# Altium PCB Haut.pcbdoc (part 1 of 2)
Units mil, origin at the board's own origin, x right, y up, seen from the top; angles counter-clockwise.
Board outline 4330.8 x 4330.8 mil, 2 copper layers (Top Layer, Bottom Layer), stack 62.2 mil thick; 77 components, 45 nets, 290 pads, 215 vias.
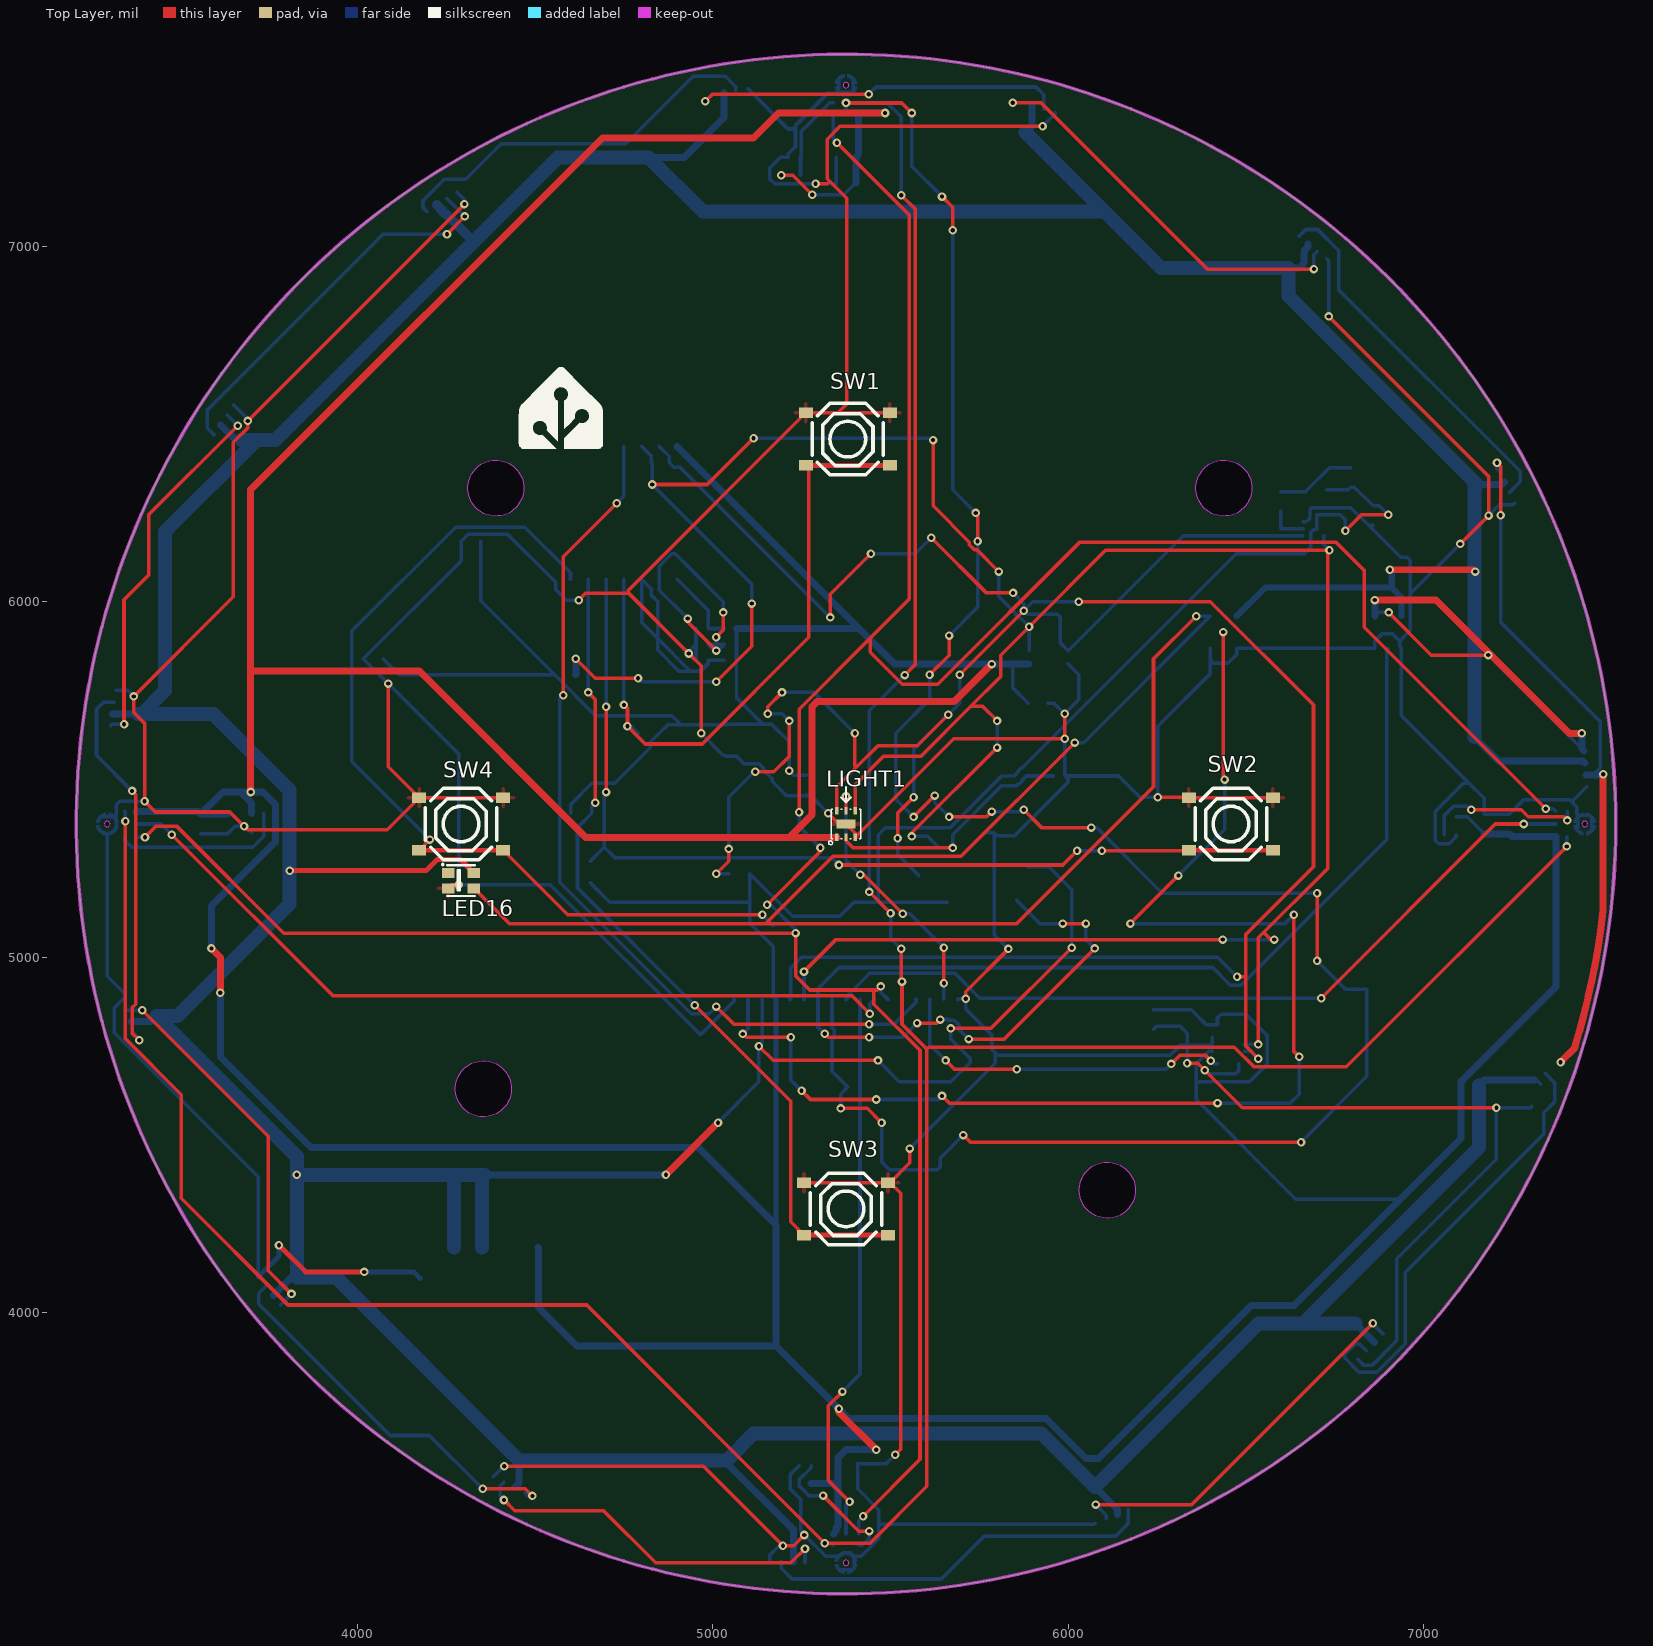
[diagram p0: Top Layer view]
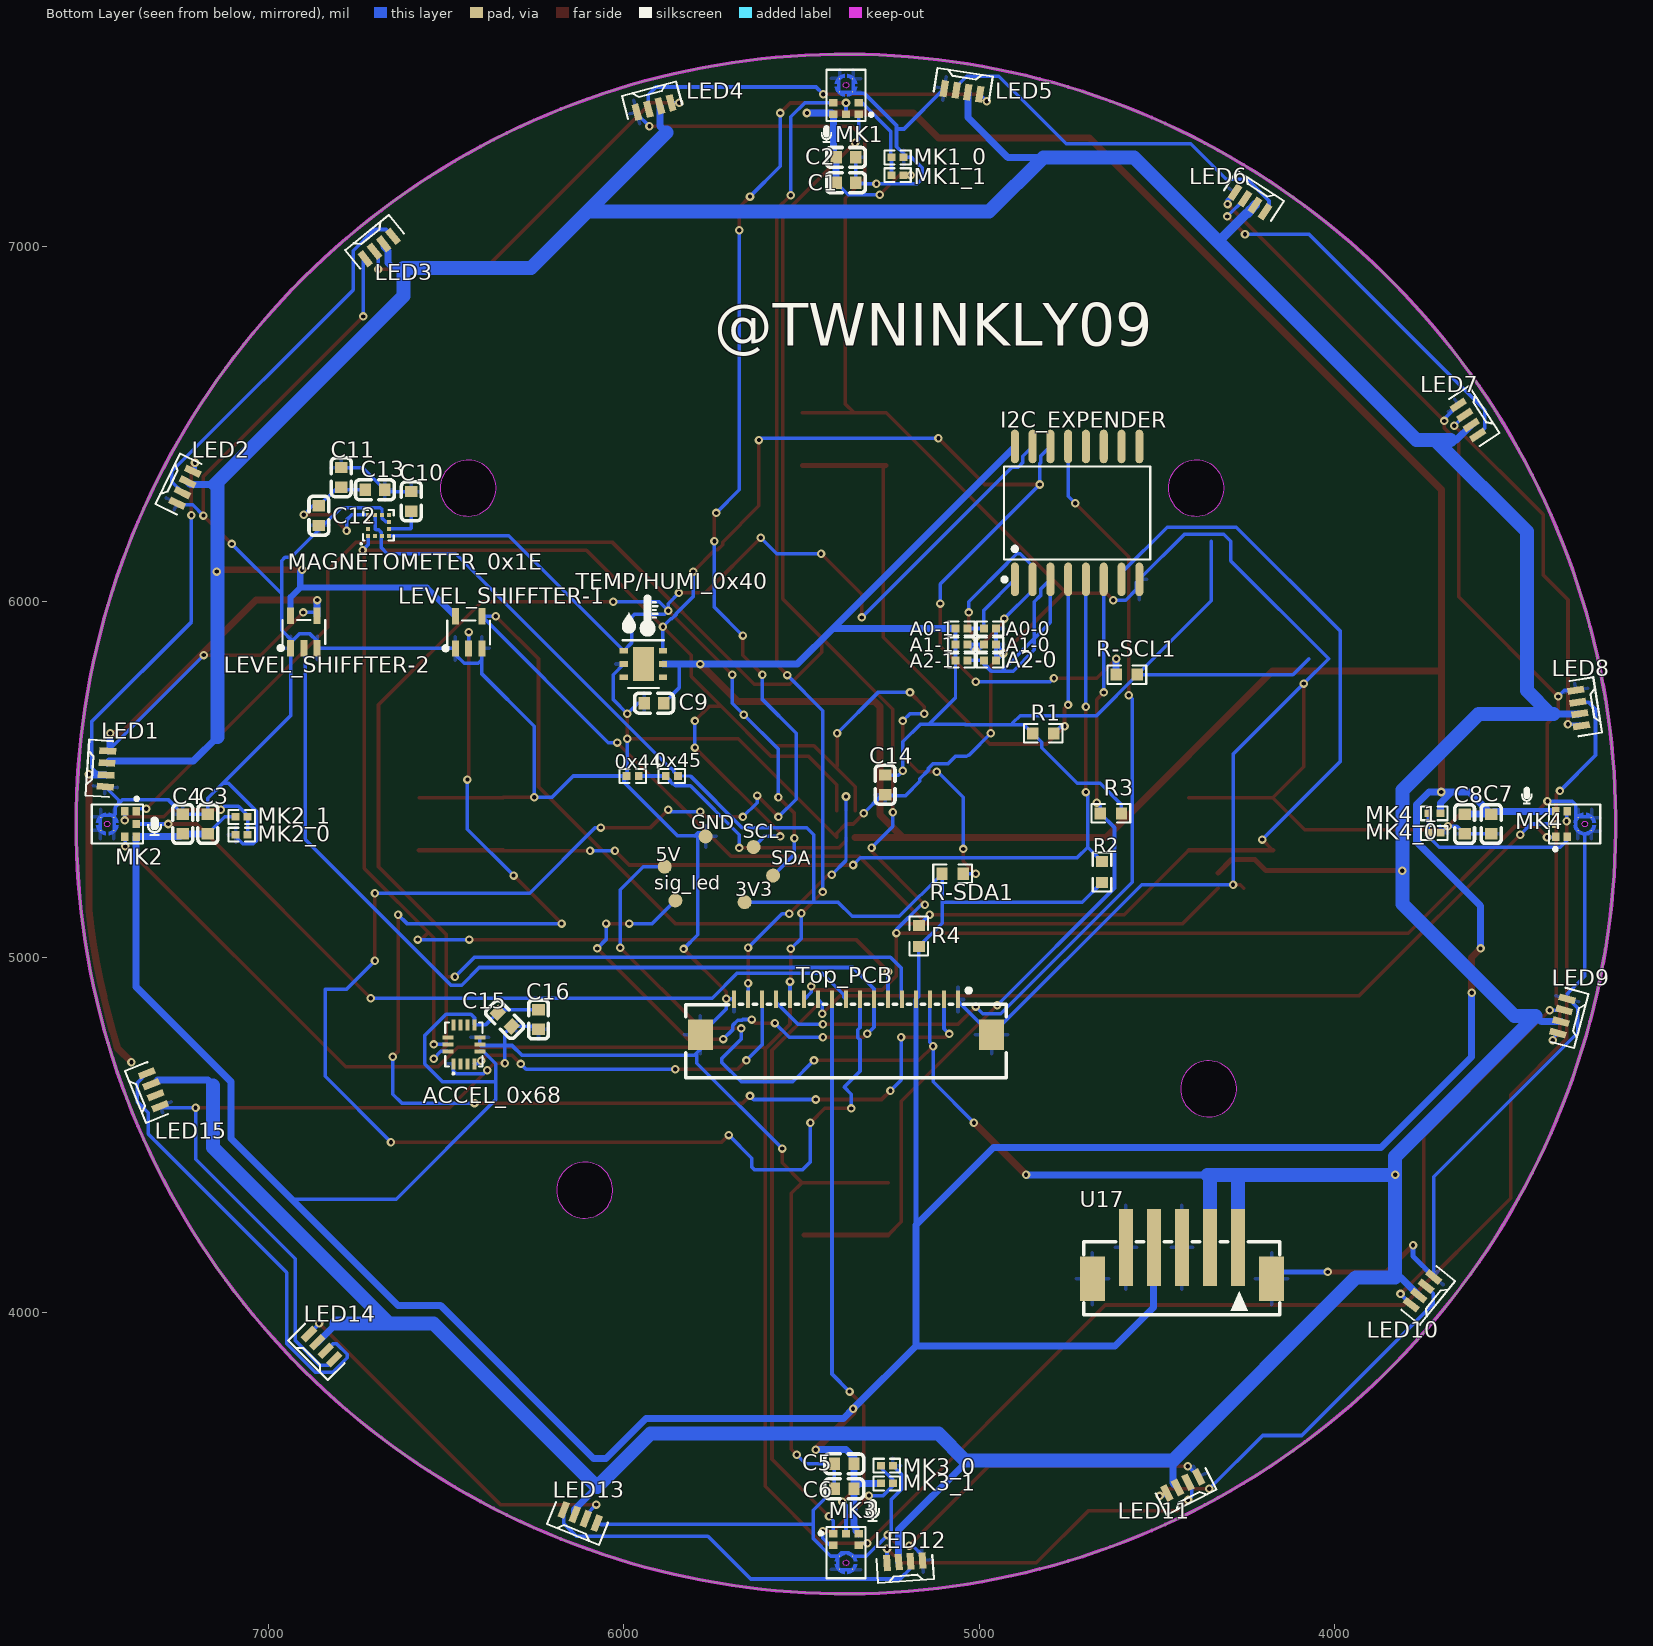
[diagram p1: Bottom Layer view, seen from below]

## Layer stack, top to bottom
Top Solder Mask Layer: solder mask 0.4, Dk 3.3
Top Layer: signal copper 1.4
Dielectric1: surface 59.4, FR4, Dk 4.5
Bottom Layer: signal copper 1.4
Bottom Solder Mask Layer: solder mask 0.4, Dk 3.3

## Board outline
7539.8,5374.4 ccw(c5374.4,5374.4) 3209.1,5374.4 ccw(c5374.4,5374.4)
cut-out: 4433.1,4629.4 4432.8,4621.6 4431.6,4613.8 4429.6,4606.2 4427,4598.8 4423.6,4591.7 4419.5,4585 4414.7,4578.8 4409.4,4573 4403.5,4567.8 4397.1,4563.3 4390.3,4559.3 4383.2,4556.1 4375.7,4553.6 4368.1,4551.9 4360.3,4550.9 4352.4,4550.7 4344.6,4551.3 4336.9,4552.6 4329.3,4554.8 4322,4557.6 4315,4561.2 4308.4,4565.5 4302.3,4570.4 4296.7,4575.8 4291.6,4581.9 4287.2,4588.3 4283.5,4595.2 4280.4,4602.5 4278.1,4610 4276.5,4617.7 4275.8,4625.5 4275.8,4633.3 4276.5,4641.1 4278.1,4648.8 4280.4,4656.3 4283.5,4663.6 4287.2,4670.5 4291.6,4676.9 4296.7,4683 4302.3,4688.4 4308.4,4693.3 4315,4697.6 4322,4701.2 4329.3,4704 4336.9,4706.2 4344.6,4707.5 4352.4,4708.1 4360.3,4707.9 4368.1,4706.9 4375.7,4705.2 4383.2,4702.7 4390.3,4699.5 4397.1,4695.5 4403.5,4691 4409.4,4685.8 4414.7,4680 4419.5,4673.8 4423.6,4667.1 4427,4660 4429.6,4652.6 4431.6,4645 4432.8,4637.2
cut-out: 4468.1,6319.3 4467.8,6311.4 4466.6,6303.7 4464.6,6296.1 4462,6288.7 4458.6,6281.6 4454.5,6274.9 4449.7,6268.7 4444.4,6262.9 4438.5,6257.7 4432.1,6253.1 4425.3,6249.2 4418.2,6246 4410.7,6243.5 4403.1,6241.7 4395.3,6240.8 4387.4,6240.6 4379.6,6241.2 4371.9,6242.5 4364.3,6244.6 4357,6247.5 4350,6251.1 4343.4,6255.4 4337.3,6260.2 4331.7,6265.7 4326.6,6271.7 4322.2,6278.2 4318.5,6285.1 4315.4,6292.4 4313.1,6299.9 4311.5,6307.5 4310.8,6315.4 4310.8,6323.2 4311.5,6331 4313.1,6338.7 4315.4,6346.2 4318.5,6353.4 4322.2,6360.3 4326.6,6366.8 4331.7,6372.8 4337.3,6378.3 4343.4,6383.2 4350,6387.5 4357,6391.1 4364.3,6393.9 4371.9,6396.1 4379.6,6397.4 4387.4,6398 4395.3,6397.8 4403.1,6396.8 4410.7,6395.1 4418.2,6392.6 4425.3,6389.4 4432.1,6385.4 4438.5,6380.8 4444.4,6375.7 4449.7,6369.9 4454.5,6363.6 4458.6,6356.9 4462,6349.9 4464.6,6342.5 4466.6,6334.9 4467.8,6327.1
cut-out: 6516.1,6319.3 6515.7,6311.4 6514.6,6303.7 6512.6,6296.1 6510,6288.7 6506.6,6281.6 6502.5,6274.9 6497.7,6268.7 6492.4,6262.9 6486.5,6257.7 6480.1,6253.1 6473.3,6249.2 6466.2,6246 6458.7,6243.5 6451.1,6241.7 6443.3,6240.8 6435.4,6240.6 6427.6,6241.2 6419.9,6242.5 6412.3,6244.6 6405,6247.5 6398,6251.1 6391.4,6255.4 6385.3,6260.2 6379.7,6265.7 6374.6,6271.7 6370.2,6278.2 6366.5,6285.1 6363.4,6292.4 6361.1,6299.9 6359.5,6307.5 6358.8,6315.4 6358.8,6323.2 6359.5,6331 6361.1,6338.7 6363.4,6346.2 6366.5,6353.4 6370.2,6360.3 6374.6,6366.8 6379.7,6372.8 6385.3,6378.3 6391.4,6383.2 6398,6387.5 6405,6391.1 6412.3,6393.9 6419.9,6396.1 6427.6,6397.4 6435.4,6398 6443.3,6397.8 6451.1,6396.8 6458.7,6395.1 6466.2,6392.6 6473.3,6389.4 6480.1,6385.4 6486.5,6380.8 6492.4,6375.7 6497.7,6369.9 6502.5,6363.6 6506.6,6356.9 6510,6349.9 6512.6,6342.5 6514.6,6334.9 6515.7,6327.1
cut-out: 6188.1,4344.4 6187.8,4336.6 6186.6,4328.8 6184.6,4321.2 6182,4313.8 6178.6,4306.7 6174.5,4300 6169.7,4293.8 6164.4,4288 6158.5,4282.8 6152.1,4278.3 6145.3,4274.3 6138.2,4271.1 6130.7,4268.6 6123.1,4266.9 6115.3,4265.9 6107.4,4265.7 6099.6,4266.3 6091.9,4267.6 6084.3,4269.8 6077,4272.6 6070,4276.2 6063.4,4280.5 6057.3,4285.4 6051.7,4290.8 6046.6,4296.9 6042.2,4303.3 6038.5,4310.2 6035.4,4317.5 6033.1,4325 6031.5,4332.7 6030.8,4340.5 6030.8,4348.3 6031.5,4356.1 6033.1,4363.8 6035.4,4371.3 6038.5,4378.6 6042.2,4385.5 6046.6,4391.9 6051.7,4398 6057.3,4403.4 6063.4,4408.3 6070,4412.6 6077,4416.2 6084.3,4419 6091.9,4421.2 6099.6,4422.5 6107.4,4423.1 6115.3,4422.9 6123.1,4421.9 6130.7,4420.2 6138.2,4417.7 6145.3,4414.5 6152.1,4410.5 6158.5,4406 6164.4,4400.8 6169.7,4395 6174.5,4388.8 6178.6,4382.1 6182,4375 6184.6,4367.6 6186.6,4360 6187.8,4352.2

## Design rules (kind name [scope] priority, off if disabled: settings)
BoardOutlineClearance copperThickness1oz [All] p0: genericclearance=10 ignorepadtopadclearanceinfootprint=FALSE except(0: Arc-SplitContinuation Track-SplitContinuation SMDPad-SplitContinuation THPad-SplitContinuation Via-SplitContinuation Fill-SplitContinuation Poly-SplitContinuation Region-SplitContinuation Text-SplitContinuation)
BoardOutlineClearance copperThickness2oz [All] p0: genericclearance=10 ignorepadtopadclearanceinfootprint=FALSE except(0: Arc-SplitContinuation Track-SplitContinuation SMDPad-SplitContinuation THPad-SplitContinuation Via-SplitContinuation Fill-SplitContinuation Poly-SplitContinuation Region-SplitContinuation Text-SplitContinuation)
BoardOutlineClearance Plane_innerPlane [All] p0: genericclearance=10 ignorepadtopadclearanceinfootprint=FALSE except(0: Arc-SplitContinuation Track-SplitContinuation SMDPad-SplitContinuation THPad-SplitContinuation Via-SplitContinuation Fill-SplitContinuation Poly-SplitContinuation Region-SplitContinuation Text-SplitContinuation)
BoardOutlineClearance Copper_copperRegion [All] p0: genericclearance=10 ignorepadtopadclearanceinfootprint=FALSE except(0: Arc-SplitContinuation Track-SplitContinuation SMDPad-SplitContinuation THPad-SplitContinuation Via-SplitContinuation Fill-SplitContinuation Poly-SplitContinuation Region-SplitContinuation Text-SplitContinuation)
BoardOutlineClearance otherClearance [All] p0: genericclearance=10 ignorepadtopadclearanceinfootprint=FALSE except(0: Arc-SplitContinuation Track-SplitContinuation SMDPad-SplitContinuation THPad-SplitContinuation Via-SplitContinuation Fill-SplitContinuation Poly-SplitContinuation Region-SplitContinuation Text-SplitContinuation)
Clearance copperThickness1oz [All] p1: gap=7 ignorepadtopadclearanceinfootprint=FALSE
Clearance copperThickness2oz [All] p1: gap=7 ignorepadtopadclearanceinfootprint=FALSE
Clearance Plane_innerPlane [All] p1: gap=7 ignorepadtopadclearanceinfootprint=FALSE
Clearance Copper_copperRegion [All] p1: gap=7 ignorepadtopadclearanceinfootprint=FALSE
Clearance otherClearance [All] p1: gap=7 ignorepadtopadclearanceinfootprint=FALSE
DiffPairsRouting differentialPair [All] p1: maxuncoupledlength=10 minlimit=6 maxlimit=Infinity mostfreqgap=6 toplayer_minwidth=5 toplayer_prefwidth=10 toplayer_maxwidth=100 bottomlayer_minwidth=5 bottomlayer_prefwidth=10 bottomlayer_maxwidth=100
PasteMaskExpansion pasteMaskExpansion [All] p1: expansion=0
PlaneConnect innerPlane [All] p1: planeconnectstyle=Relief reliefexpansion=20 reliefentries=4 reliefconductorwidth=10 reliefairgap=10
PolygonConnect copperRegion [All] p1: connectstyle=Relief reliefentries=4 reliefconductorwidth=10 polygonreliefangle="90 Angle" airgapwidth=10
RoutingVias viaSize [All] p1: viastyle="Through Hole" holewidth=12.0078 minholewidth=11.811 maxholewidth=248.0314 width=12.0078 minwidth=11.811 maxwidth=248.0314
SolderMaskExpansion solderMaskExpansion [IsVia] p1: useseparateexpansions=TRUE expansion=-1000 expansionbottom=-1000
SolderMaskExpansion solderMaskExpansion [All] p2: useseparateexpansions=TRUE expansion=2 expansionbottom=2
Width copperThickness1oz [All] p1: maxlimit=100 minlimit=5 preferedwidth=10
Width copperThickness2oz [All] p1: maxlimit=100 minlimit=8 preferedwidth=10

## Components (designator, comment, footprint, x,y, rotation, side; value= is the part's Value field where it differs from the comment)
0x44 "0Ω" R0402 5974.4,5509.4 r180 bottom
0x45 "0Ω" R0402 5864.4,5509.4 r180 bottom
3V3 "" Test-Point-0.5mm 5659.4,5154.4 r180 bottom
5V "" Test-Point-0.5mm 5884.4,5254.4 r180 bottom
A0-0 "0Ω" R0402 4969.4,5924.4 r0 bottom locked
A0-1 "0Ω" R0402 5049.4,5924.4 r180 bottom locked
A1-0 "0Ω" R0402 4969.4,5879.4 r180 bottom locked
A1-1 "0Ω" R0402 5049.4,5879.4 r180 bottom locked
A2-0 "0Ω" R0402 4969.4,5834.4 r180 bottom locked
A2-1 "0Ω" R0402 5049.4,5834.4 r180 bottom locked
ACCEL_0x68 "BMI160" LGA-14_L3.0-W2.5-P0.50-BL 6449.4,4754.4 r180 bottom
C1 "200pF" C0603#1 5374.4,7178.1 r180 bottom
C2 "100nF" C0603#1 5374.4,7249.4 r180 bottom
C3 "200pF" C0603#1 7169.4,5374.4 r90 bottom
C4 "100nF" C0603#1 7240,5374.4 r90 bottom locked
C5 "200pF" C0603#1 5379.4,3574.4 r0 bottom
C6 "100nF" C0603#1 5379.4,3504.4 r0 bottom
C7 "200pF" C0603#1 3559.4,5374.4 r270 bottom
C8 "100nF" C0603#1 3634.4,5374.4 r270 bottom
C9 "100nF" C0603#1 5914.4,5714.4 r0 bottom
C10 "220nF" C0603#2 6597,6282 r270 bottom
C11 "100nF" C0603#1 6794.4,6349.4 r270 bottom
C12 "100nF" C0603#2 6857,6241.8 r90 bottom
C13 "10uF" C0603#1 6699.4,6314.4 r0 bottom
C14 "100nF" C0603#1 5264.4,5484.4 r90 bottom
C15 "100nF" C0603#1 6334.4,4824.4 r45 bottom
C16 "100nF" C0603#1 6239.4,4824.4 r90 bottom
GND "" Test-Point-0.5mm 5769.4,5339.4 r180 bottom
I2C_EXPENDER "PCA9554DW" SOIC-16_L10.3-W7.5-P1.27-LS10.3-BL 4724.4,6249.4 r180 bottom locked
LED1 "WS2812C-4020" LED-SMD_4P-L4.0-W1.7-R#1 7454.4,5529.4 r94 bottom locked
LED2 "WS2812C-4020" LED-SMD_4P-L4.0-W1.7-R#2 7233.6,6321.7 r116 bottom locked
LED3 "WS2812C-4020" LED-SMD_4P-L4.0-W1.7-R#3 6687.6,6996 r141 bottom locked
LED4 "WS2812C-4020" LED-SMD_4P-L4.0-W1.7-R#4 5914.5,7389.9 r165 bottom locked
LED5 "WS2812C-4020" LED-SMD_4P-L4.0-W1.7-R#5 5048,7435.3 r189 bottom locked
LED6 "WS2812C-4020" LED-SMD_4P-L4.0-W1.7-R#6 4238,7124.4 r213 bottom locked
LED7 "WS2812C-4020" LED-SMD_4P-L4.0-W1.7-R#1 3624.4,6510.9 r237 bottom locked
LED8 "WS2812C-4020" LED-SMD_4P-L4.0-W1.7-R#7 3313.5,5700.8 r261 bottom locked
LED9 "WS2812C-4020" LED-SMD_4P-L4.0-W1.7-R#8 3358.9,4834.3 r285 bottom locked
LED10 "WS2812C-4020" LED-SMD_4P-L4.0-W1.7-R#9 3752.8,4061.3 r309 bottom locked
LED11 "WS2812C-4020" LED-SMD_4P-L4.0-W1.7-R#1 4427.1,3515.2 r333 bottom locked
LED12 "WS2812C-4020" LED-SMD_4P-L4.0-W1.7-R#6 5209.4,3299.4 r356 bottom locked
LED13 "WS2812C-4020" LED-SMD_4P-L4.0-W1.7-R#10 6122.2,3426.4 r22 bottom locked
LED14 "WS2812C-4020" LED-SMD_4P-L4.0-W1.7-R#2 6849.4,3904.4 r45 bottom locked
LED15 "WS2812C-4020" LED-SMD_4P-L4.0-W1.7-R#11 7322.4,4626.6 r68 bottom locked
LED16 "WS2812B-2020" LED-SMD_4P-L2.0-W2.0-TL_WS2812B-2020 4291.7,5215.1 r0 top locked
LEVEL_SHIFFTER-1 "74AHCT1G125GV" SOT-23-5_L3.0-W1.7-P0.95-LS2.8-BL#1 6435.9,5913.6 r180 bottom
LEVEL_SHIFFTER-2 "74AHCT1G125GV" SOT-23-5_L3.0-W1.7-P0.95-LS2.8-BL#2 6899.4,5914.4 r180 bottom
LIGHT1 "OPT3001DNPR" USON6_L2.1-W2.1-P0.65-BL-EP 5374.4,5374.4 r0 top locked
MAGNETOMETER_0x1E "LIS2MDLTR" VLGA-12_L2.0-W2.0-P0.50-BL 6689.4,6214.4 r180 bottom
MK1 "SPH0645LM4H-B-8" MIC-SMD_6P-L3.5-W2.7-P0.90-BL#1 5374.4,7421.6 r90 bottom locked
MK1_0 "0Ω" R0402 5229.4,7249.4 r180 bottom
MK1_1 "0Ω" R0402 5229.4,7199.4 r180 bottom
MK2 "SPH0645LM4H-B-8" MIC-SMD_6P-L3.5-W2.7-P0.90-BL#2 7421.7,5374.4 r0 bottom locked
MK2_0 "0Ω" R0402 7074.4,5344.4 r0 bottom
MK2_1 "0Ω" R0402 7074.4,5394.4 r0 bottom
MK3 "SPH0645LM4H-B-8" MIC-SMD_6P-L3.5-W2.7-P0.90-BL#1 5374.4,3327.2 r270 bottom locked
MK3_0 "0Ω" R0402 5259.4,3569.4 r180 bottom
MK3_1 "0Ω" R0402 5259.4,3519.4 r0 bottom
MK4 "SPH0645LM4H-B-8" MIC-SMD_6P-L3.5-W2.7-P0.90-BL#1 3327.2,5374.4 r180 bottom locked
MK4_0 "0Ω" R0402 3719.4,5349.4 r180 bottom
MK4_1 "0Ω" R0402 3719.4,5404.4 r180 bottom
R1 "10kΩ" R0603 4819.4,5629.4 r180 bottom
R2 "10kΩ" R0603 4654.4,5239.4 r90 bottom
R3 "10kΩ" R0603 4629.4,5404.4 r0 bottom
R4 "10kΩ" R0603 5169.4,5059.4 r90 bottom
R-SCL1 "4.7kΩ" R0603 4584.4,5794.4 r180 bottom
R-SDA1 "4.7kΩ" R0603 5074.4,5234.4 r0 bottom
SCL "" Test-Point-0.5mm 5634.4,5309.4 r180 bottom
SDA "" Test-Point-0.5mm 5579.4,5229.4 r180 bottom
sig_led "sig_led" Test-Point-0.5mm 5854.4,5159.4 r180 bottom
SW1 "TS-1187A-B-A-B" SW-SMD_4P-L5.1-W5.1-P3.70-LS6.5-TL_H1.5 5379.4,6457.1 r0 top locked
SW2 "TS-1187A-B-A-B" SW-SMD_4P-L5.1-W5.1-P3.70-LS6.5-TL_H1.5 6457.1,5374.4 r0 top locked
SW3 "TS-1187A-B-A-B" SW-SMD_4P-L5.1-W5.1-P3.70-LS6.5-TL_H1.5 5374.4,4291.7 r0 top locked
SW4 "TS-1187A-B-A-B" SW-SMD_4P-L5.1-W5.1-P3.70-LS6.5-TL_H1.5 4291.7,5374.4 r0 top locked
TEMP/HUMI_0x40 "Sensor_Humidity_HDC1080" Package_SON:Texas_PWSON-N6 5944.4,5824.4 r180 bottom
Top_PCB "ZX-1.0FPC-2H-QFX17P" FPC-SMD_17P-P1.00_ZX-1.0FPC-2H-QFX17P 5374.4,4831.1 r180 bottom locked
U17 "B5B-PH-SM4-TB(LF)(SN)" CONN-SMD_5P-P2.00_B6B-PH-SM4-TB-LF-SN 4429.4,4139.4 r180 bottom

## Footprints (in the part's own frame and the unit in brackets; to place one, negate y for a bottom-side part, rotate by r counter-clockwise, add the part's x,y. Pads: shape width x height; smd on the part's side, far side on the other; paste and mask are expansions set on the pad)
C0603#1 [mil]
  rect 31.5x35.4 smd: 1(-27.6,0) 2(27.6,0)
  silkscreen extent -55,-28 55,28
C0603#2 [mil]
  rect 31.5x35.4 smd: 1(-27.5,0) 2(27.6,0)
  silkscreen extent -55,-28 55,28
CONN-SMD_5P-P2.00_B6B-PH-SM4-TB-LF-SN [mil]
  rect 39.4x216.5 smd: 1(157.5,44.3) 2(78.7,44.3) 3(0,44.3) 4(-78.7,44.3) 5(-157.5,44.3)
  rect 70.9x126 smd: 6(252,-44.3) 7(-252,-44.3)
  silkscreen extent -276,-146 276,60
FPC-SMD_17P-P1.00_ZX-1.0FPC-2H-QFX17P [mil]
  rect 11.8x49.2 smd paste+0 mask+2: 1(315,49.7) 2(275.6,49.7) 3(236.2,49.7) 4(196.8,49.7) 5(157.5,49.7) 6(118.1,49.7) 7(78.7,49.7) 8(39.4,49.7) 9(0,49.7) 10(-39.4,49.7) 11(-78.7,49.7) 12(-118.1,49.7) 13(-157.5,49.7) 14(-196.9,49.7) 15(-236.2,49.7) 16(-275.6,49.7) 17(-315,49.7)
  rect 70.9x86.6 smd paste+0 mask+2: 18(-409.5,-49.7) 19(409.4,-49.7)
  silkscreen extent -451,-171 451,81
LED-SMD_4P-L2.0-W2.0-TL_WS2812B-2020 [mil]
  rect 35.4x27.6 smd: 1(-36,21.6) 2(-36,-21.7) 3(36.1,-21.7) 4(36.1,21.6)
  silkscreen extent -51,-43 39,45
LED-SMD_4P-L4.0-W1.7-R#1 [mil]
  rect 19.7x47.2 smd: 1(50.22,0) 2(16.74,-0.03) 3(-16.74,0.03) 4(-50.22,0)
  silkscreen extent -79,-13 79,54
LED-SMD_4P-L4.0-W1.7-R#2 [mil]
  rect 19.7x47.2 smd: 1(50.18,0) 2(16.68,0.01) 3(-16.68,-0.01) 4(-50.18,0)
  silkscreen extent -79,-13 79,54
LED-SMD_4P-L4.0-W1.7-R#3 [mil]
  rect 19.7x47.2 smd: 1(50.27,-0.05) 2(16.71,-0.02) 3(-16.71,0.02) 4(-50.2,-0.01)
  silkscreen extent -79,-13 79,54
LED-SMD_4P-L4.0-W1.7-R#4 [mil]
  rect 19.7x47.2 smd: 1(50.21,0) 2(16.76,-0.04) 3(-16.66,0.01) 4(-50.12,-0.03)
  silkscreen extent -79,-13 79,54
LED-SMD_4P-L4.0-W1.7-R#5 [mil]
  rect 19.7x47.2 smd: 1(50.21,0.06) 2(16.7,0.01) 3(-16.7,-0.01) 4(-50.23,0.04)
  silkscreen extent -79,-13 79,54
LED-SMD_4P-L4.0-W1.7-R#6 [mil]
  rect 19.7x47.2 smd: 1(50.23,-0.05) 2(16.78,0.05) 3(-16.7,0.01) 4(-50.18,-0.03)
  silkscreen extent -79,-13 79,54
LED-SMD_4P-L4.0-W1.7-R#7 [mil]
  rect 19.7x47.2 smd: 1(50.23,0.04) 2(16.7,-0.01) 3(-16.8,0.03) 4(-50.21,0.06)
  silkscreen extent -79,-13 79,54
LED-SMD_4P-L4.0-W1.7-R#8 [mil]
  rect 19.7x47.2 smd: 1(50.12,-0.03) 2(16.66,0.01) 3(-16.76,-0.04) 4(-50.21,0)
  silkscreen extent -79,-13 79,54
LED-SMD_4P-L4.0-W1.7-R#9 [mil]
  rect 19.7x47.2 smd: 1(50.27,0.05) 2(16.79,0.08) 3(-16.71,-0.02) 4(-50.2,0.01)
  silkscreen extent -79,-13 79,54
LED-SMD_4P-L4.0-W1.7-R#10 [mil]
  rect 19.7x47.2 smd: 1(50.16,-0.01) 2(16.69,0.06) 3(-16.73,0.03) 4(-50.25,-0.03)
  silkscreen extent -79,-13 79,54
LED-SMD_4P-L4.0-W1.7-R#11 [mil]
  rect 19.7x47.2 smd: 1(50.25,-0.03) 2(16.73,0.03) 3(-16.69,0.06) 4(-50.16,-0.01)
  silkscreen extent -79,-13 79,54
LGA-14_L3.0-W2.5-P0.50-BL [mil]
  rect 11x30.9 smd: 1(-29.5,-54.8) 2(-9.8,-54.8) 3(9.8,-54.8) 4(29.5,-54.8) 8(29.5,54.8) 9(9.8,54.8) 10(-9.8,54.8) 11(-29.5,54.8)
  rect 30.9x11 smd: 5(45,-19.7) 6(45,0) 7(45,19.7) 12(-45,19.7) 13(-45,0) 14(-45,-19.7)
  silkscreen extent -52,-85 52,62
MIC-SMD_6P-L3.5-W2.7-P0.90-BL#1 [mil]
  rect 20.5x23.6 smd paste+0 mask+2: 1(-50.6,-35.4) 2(-18.2,-35.4) 4(-18.2,35.4) 5(-50.6,35.4) 6(-50.6,0)
  round 3.4 smd: 3(12.7,-18.1) 3(12.7,18.1) 3(48.9,-18.1) 3(48.9,18.1)
  Top Layer region: -1,3.9 9,3.9 9,3.9 9.3,5.2 9.6,6.5 10,7.8 10.6,9 11.1,10.2 11.8,11.4 12.5,12.6 13.3,13.7 14.2,14.7 15.1,15.7 16.1,16.6 17.2,17.5 18.2,18.3 19.4,19 20.6,19.7 21.8,20.3 23,20.8 24.3,21.2 25.6,21.6 27,21.8 27,31.7 26.9,31.8 25.3,31.5 23.7,31.2 22.1,30.8 20.6,30.3 19,29.8 17.5,29.1 16,28.4 14.6,27.6 13.2,26.8 11.9,25.8 10.6,24.8 9.4,23.8 8.2,22.6 7,21.5 6,20.2 5,18.9 4.1,17.6 3.2,16.2 2.4,14.8 1.7,13.3 1,11.8 0.5,10.3 0,8.7 -0.4,7.1 -0.7,5.5 -1,3.9
  Top Layer region: 27,-31.8 27,-21.8 27,-21.8 25.6,-21.5 24.3,-21.2 23,-20.8 21.8,-20.2 20.6,-19.7 19.4,-19 18.2,-18.3 17.2,-17.5 16.1,-16.6 15.1,-15.7 14.2,-14.7 13.3,-13.6 12.5,-12.5 11.8,-11.4 11.1,-10.2 10.6,-9 10,-7.8 9.6,-6.5 9.3,-5.2 9,-3.8 -0.9,-3.8 -1,-3.9 -0.7,-5.5 -0.4,-7.1 0,-8.7 0.5,-10.2 1,-11.8 1.7,-13.3 2.4,-14.7 3.2,-16.2 4.1,-17.6 5,-18.9 6,-20.2 7,-21.4 8.2,-22.6 9.4,-23.7 10.6,-24.8 11.9,-25.8 13.2,-26.7 14.6,-27.6 16,-28.4 17.5,-29.1 19,-29.7 20.6,-30.3 22.1,-30.8 23.7,-31.2 25.3,-31.5 26.9,-31.8
  Top Layer region: 62.6,-3.8 52.6,-3.8 52.6,-3.8 52.4,-5.2 52,-6.5 51.6,-7.8 51.1,-9 50.5,-10.2 49.8,-11.4 49.1,-12.5 48.3,-13.6 47.4,-14.7 46.5,-15.7 45.5,-16.6 44.4,-17.5 43.4,-18.3 42.2,-19 41,-19.7 39.8,-20.2 38.6,-20.8 37.3,-21.2 36,-21.5 34.7,-21.8 34.7,-31.7 34.7,-31.8 36.3,-31.5 37.9,-31.2 39.5,-30.8 41.1,-30.3 42.6,-29.8 44.1,-29.1 45.6,-28.4 47,-27.6 48.4,-26.7 49.7,-25.8 51,-24.8 52.2,-23.7 53.4,-22.6 54.6,-21.4 55.6,-20.2 56.6,-18.9 57.5,-17.6 58.4,-16.2 59.2,-14.7 59.9,-13.3 60.6,-11.8 61.1,-10.2 61.6,-8.7 62,-7.1 62.3,-5.5 62.6,-3.9
  Top Layer region: 34.6,31.8 34.6,21.8 34.7,21.8 36,21.6 37.3,21.2 38.6,20.8 39.8,20.3 41,19.7 42.2,19 43.4,18.3 44.4,17.5 45.5,16.6 46.5,15.7 47.4,14.7 48.3,13.7 49.1,12.6 49.8,11.4 50.5,10.2 51.1,9 51.6,7.8 52,6.5 52.4,5.2 52.6,3.9 62.5,3.9 62.6,3.9 62.3,5.5 62,7.1 61.6,8.7 61.1,10.3 60.6,11.8 59.9,13.3 59.2,14.8 58.4,16.2 57.6,17.6 56.6,18.9 55.6,20.2 54.6,21.4 53.4,22.6 52.3,23.8 51,24.8 49.7,25.8 48.4,26.8 47,27.6 45.6,28.4 44.1,29.1 42.6,29.8 41.1,30.3 39.5,30.8 37.9,31.2 36.3,31.5 34.7,31.8
  Board Outline Layer lines w0.1: 31,-7.9 33.4,-7.5 35.6,-6.4 37.4,-4.6 38.5,-2.4 38.9,0 38.5,2.4 37.4,4.6 35.6,6.4 33.4,7.5 31,7.9 28.6,7.5 26.4,6.4 24.6,4.6 23.5,2.4 23.1,0 23.5,-2.4 24.6,-4.6 26.4,-6.4 28.6,-7.5 31,-7.9
  Board Outline Layer region: 38.9,0 38.5,-2.4 37.4,-4.6 35.6,-6.4 33.4,-7.5 31,-7.9 28.6,-7.5 26.4,-6.4 24.6,-4.6 23.5,-2.4 23.1,0 23.5,2.4 24.6,4.6 26.4,6.4 28.6,7.5 31,7.9 33.4,7.5 35.6,6.4 37.4,4.6 38.5,2.4
  Board Outline Layer region: 38.9,0 38.5,-2.4 37.4,-4.6 35.6,-6.4 33.4,-7.5 31,-7.9 28.6,-7.5 26.4,-6.4 24.6,-4.6 23.5,-2.4 23.1,0 23.5,2.4 24.6,4.6 26.4,6.4 28.6,7.5 31,7.9 33.4,7.5 35.6,6.4 37.4,4.6 38.5,2.4
  Multi-Layer board cut-out: 38.9,0 38.5,-2.4 37.4,-4.6 35.6,-6.4 33.4,-7.5 31,-7.9 28.6,-7.5 26.4,-6.4 24.6,-4.6 23.5,-2.4 23.1,0 23.5,2.4 24.6,4.6 26.4,6.4 28.6,7.5 31,7.9 33.4,7.5 35.6,6.4 37.4,4.6 38.5,2.4
  silkscreen extent -69,-76 74,55
MIC-SMD_6P-L3.5-W2.7-P0.90-BL#2 [mil]
  rect 20.5x23.6 smd paste+0 mask+2: 1(-50.7,-35.4) 2(-18.3,-35.4) 4(-18.3,35.4) 5(-50.7,35.4) 6(-50.7,0)
  round 3.4 smd: 3(12.6,-18.1) 3(12.6,18.1) 3(48.8,-18.1) 3(48.8,18.1)
  Top Layer region: -1.1,3.8 8.9,3.8 8.9,3.8 9.2,5.2 9.5,6.5 9.9,7.8 10.5,9 11,10.2 11.7,11.4 12.4,12.6 13.2,13.6 14.1,14.7 15,15.7 16,16.6 17.1,17.5 18.2,18.3 19.3,19 20.5,19.7 21.7,20.2 22.9,20.8 24.2,21.2 25.5,21.5 26.9,21.8 26.9,31.7 26.8,31.8 25.2,31.5 23.6,31.2 22,30.8 20.5,30.3 18.9,29.8 17.4,29.1 16,28.4 14.5,27.6 13.1,26.7 11.8,25.8 10.5,24.8 9.3,23.8 8.1,22.6 7,21.4 5.9,20.2 4.9,18.9 4,17.6 3.1,16.2 2.3,14.8 1.6,13.3 1,11.8 0.4,10.2 -0.1,8.7 -0.5,7.1 -0.8,5.5 -1.1,3.9
  Top Layer region: 26.9,-31.8 26.9,-21.8 26.9,-21.8 25.5,-21.6 24.2,-21.2 22.9,-20.8 21.7,-20.3 20.5,-19.7 19.3,-19 18.2,-18.3 17.1,-17.5 16,-16.6 15,-15.7 14.1,-14.7 13.2,-13.6 12.4,-12.6 11.7,-11.4 11.1,-10.2 10.5,-9 9.9,-7.8 9.5,-6.5 9.2,-5.2 8.9,-3.9 -1,-3.9 -1.1,-3.9 -0.8,-5.5 -0.5,-7.1 -0.1,-8.7 0.4,-10.3 1,-11.8 1.6,-13.3 2.3,-14.8 3.1,-16.2 4,-17.6 4.9,-18.9 5.9,-20.2 7,-21.4 8.1,-22.6 9.3,-23.8 10.5,-24.8 11.8,-25.8 13.1,-26.7 14.5,-27.6 16,-28.4 17.4,-29.1 18.9,-29.8 20.5,-30.3 22,-30.8 23.6,-31.2 25.2,-31.5 26.8,-31.8
  Top Layer region: 62.5,-3.8 52.5,-3.8 52.5,-3.9 52.3,-5.2 51.9,-6.5 51.5,-7.8 51,-9 50.4,-10.2 49.7,-11.4 49,-12.6 48.2,-13.6 47.3,-14.7 46.4,-15.7 45.4,-16.6 44.4,-17.5 43.3,-18.3 42.1,-19 40.9,-19.7 39.7,-20.3 38.5,-20.8 37.2,-21.2 35.9,-21.6 34.6,-21.8 34.6,-31.7 34.6,-31.8 36.2,-31.5 37.8,-31.2 39.4,-30.8 41,-30.3 42.5,-29.8 44,-29.1 45.5,-28.4 46.9,-27.6 48.3,-26.8 49.6,-25.8 50.9,-24.8 52.2,-23.8 53.3,-22.6 54.5,-21.5 55.5,-20.2 56.5,-18.9 57.5,-17.6 58.3,-16.2 59.1,-14.8 59.8,-13.3 60.5,-11.8 61,-10.3 61.5,-8.7 61.9,-7.1 62.2,-5.5 62.5,-3.9
  Top Layer region: 34.6,31.8 34.6,21.8 34.6,21.8 35.9,21.5 37.2,21.2 38.5,20.8 39.7,20.2 40.9,19.7 42.1,19 43.3,18.3 44.4,17.5 45.4,16.6 46.4,15.7 47.3,14.7 48.2,13.6 49,12.5 49.7,11.4 50.4,10.2 51,9 51.5,7.8 51.9,6.5 52.3,5.2 52.5,3.8 62.4,3.8 62.5,3.9 62.2,5.5 61.9,7.1 61.5,8.7 61,10.2 60.5,11.8 59.8,13.3 59.1,14.7 58.3,16.2 57.5,17.6 56.5,18.9 55.5,20.2 54.5,21.4 53.3,22.6 52.2,23.7 50.9,24.8 49.6,25.8 48.3,26.7 46.9,27.6 45.5,28.4 44,29.1 42.5,29.8 41,30.3 39.4,30.8 37.8,31.2 36.2,31.5 34.6,31.8
  Board Outline Layer lines w0.1: 23,0 23.4,-2.4 24.5,-4.6 26.3,-6.4 28.5,-7.5 30.9,-7.9 33.3,-7.5 35.5,-6.4 37.3,-4.6 38.4,-2.4 38.8,0 38.4,2.4 37.3,4.6 35.5,6.4 33.3,7.5 30.9,7.9 28.5,7.5 26.3,6.4 24.5,4.6 23.4,2.4 23,0
  Board Outline Layer region: 38.8,0 38.4,-2.4 37.3,-4.6 35.5,-6.4 33.3,-7.5 30.9,-7.9 28.5,-7.5 26.3,-6.4 24.5,-4.6 23.4,-2.4 23,0 23.4,2.4 24.5,4.6 26.3,6.4 28.5,7.5 30.9,7.9 33.3,7.5 35.5,6.4 37.3,4.6 38.4,2.4
  Board Outline Layer region: 38.8,0 38.4,-2.4 37.3,-4.6 35.5,-6.4 33.3,-7.5 30.9,-7.9 28.5,-7.5 26.3,-6.4 24.5,-4.6 23.4,-2.4 23,0 23.4,2.4 24.5,4.6 26.3,6.4 28.5,7.5 30.9,7.9 33.3,7.5 35.5,6.4 37.3,4.6 38.4,2.4
  Multi-Layer board cut-out: 38.8,0 38.4,-2.4 37.3,-4.6 35.5,-6.4 33.3,-7.5 30.9,-7.9 28.5,-7.5 26.3,-6.4 24.5,-4.6 23.4,-2.4 23,0 23.4,2.4 24.5,4.6 26.3,6.4 28.5,7.5 30.9,7.9 33.3,7.5 35.5,6.4 37.3,4.6 38.4,2.4
  silkscreen extent -70,-76 74,55
Package_SON:Texas_PWSON-N6 [mil]
  rect 23.6x15.7 smd paste+0 mask+0: 1(-55.1,37.4) 2(-55.1,0) 3(-55.1,-37.4) 4(55.1,-37.4) 5(55.1,0) 6(55.1,37.4)
  rect 59.1x94.5 smd paste+0 mask+0: 7(0,0)
  silkscreen extent -58,-67 58,67
R0402 [mil]
  rect 22.3x21.3 smd paste-3937 mask+2: 1(-17,0) 2(17,0)
  silkscreen extent -37,-20 37,20
R0603 [mil]
  rect 31.8x34 smd paste-3937 mask+2: 1(-29.7,0) 2(29.7,0)
  silkscreen extent -54,-26 54,26
SOIC-16_L10.3-W7.5-P1.27-LS10.3-BL [mil]
  oval 22.6x94.5 smd: 1(-175,-187) 2(-125,-187) 3(-75,-187) 4(-25,-187) 5(25,-187) 6(75,-187) 7(125,-187) 8(175,-187) 9(175,187) 10(125,187) 11(75,187) 12(25,187) 13(-25,187) 14(-75,187) 15(-125,187) 16(-175,187)
  silkscreen extent -210,-193 206,131
SOT-23-5_L3.0-W1.7-P0.95-LS2.8-BL#1 [mil]
  rect 19.3x45.6 smd: 1(-37.4,-45.4) 2(0,-45.4) 3(37.4,-45.4)
  rect 19.3x46.3 smd: 4(37.4,45.5) 5(-37.4,45.5)
  silkscreen extent -71,-51 60,34
SOT-23-5_L3.0-W1.7-P0.95-LS2.8-BL#2 [mil]
  rect 19.3x45.6 smd: 1(-37.4,-45.4) 2(0,-45.4) 3(37.4,-45.4)
  rect 19.3x46.3 smd: 4(37.4,45.4) 5(-37.4,45.4)
  silkscreen extent -71,-51 60,34
SW-SMD_4P-L5.1-W5.1-P3.70-LS6.5-TL_H1.5 [mil]
  rect 39.4x29.5 smd: 1(-118.1,73.8) 2(118.1,73.8) 3(-118.1,-73.8) 4(118.1,-73.8)
  silkscreen extent -100,-100 100,100
Test-Point-0.5mm [mil]
  round 39.4 smd: 1(0,0)
USON6_L2.1-W2.1-P0.65-BL-EP [mil]
  rect 9.8x21.7 smd: 1(-25.6,-37.4) 2(0,-37.4) 3(25.6,-37.4) 4(25.6,37.4) 5(0,37.4) 6(-25.6,37.4)
  rect 53.1x25.6 smd: 7(0,0)
  silkscreen extent -49,-59 41,41
VLGA-12_L2.0-W2.0-P0.50-BL [mil]
  rect 11.8x11.8 smd paste+0 mask+2: 1(-29.5,-29.5) 2(-9.8,-29.5) 3(9.8,-29.5) 4(29.5,-29.5) 5(29.5,-9.8) 6(29.5,9.8) 7(29.5,29.5) 8(9.8,29.5) 9(-9.8,29.5) 10(-29.5,29.5) 11(-29.5,9.8) 12(-29.5,-9.8)
  silkscreen extent -51,-54 43,43

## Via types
v1: diameter 24, hole 12, Top Layer to Bottom Layer, 215 vias

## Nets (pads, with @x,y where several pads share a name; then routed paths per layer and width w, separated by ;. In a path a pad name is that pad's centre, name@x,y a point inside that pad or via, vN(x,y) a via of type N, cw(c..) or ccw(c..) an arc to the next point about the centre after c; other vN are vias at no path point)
3V3: 0x45.2 3V3.1 A0-1.1 A1-1.1 A2-1.1 ACCEL_0x68.5 ACCEL_0x68.8 C1.1 C2.1 C3.1 C4.1 C5.1 C6.1 C7.1 C8.1 C9.1 C11.2 C12.2 C13.2 C14.2 C15.2 C16.2 I2C_EXPENDER.16 LIGHT1.1 MAGNETOMETER_0x1E.3 MAGNETOMETER_0x1E.9 MAGNETOMETER_0x1E.10 MK1.5 MK1_1.2 MK2.5 MK2_1.2 MK3.5 MK3_1.2 MK4.5 MK4_1.2 R1.1 R2.1 R3.1 R4.1 R-SCL1.2 R-SDA1.2 TEMP/HUMI_0x40.5 Top_PCB.4 U17.4 | length 25282.5
  Top Layer w9.8: v1(6779.4,6199.4) 6824.4,6244.4 v1(6899.4,6244.4)
  Top Layer w10: v1(5192.4,7199.4) 5224.4,7199.4 v1(5279.4,7144.4)
  Top Layer w19.7: v1(3589.4,5024.4) 3614.4,4999.4 v1(3614.4,4899.4) ; v1(3699.7,5464.4) 3699.7,5804.7 ; LIGHT1.1@5348.8,5337 5215.5,5337 ; v1(5354.4,3729.4) 5354.4,3719.4 v1(5459.4,3614.4) ; v1(5484.4,7374.4) 5184.4,7374.4 5114.4,7304.4 4689.4,7304.4 3699.7,6314.7 3699.7,5804.7 ; v1(5784.4,5824.4) 5678.3,5718.3 5293.3,5718.3 5279.4,5704.4 5279.4,5400.9 5215.5,5337 ; 3699.7,5804.7 4174.2,5804.7 4641.8,5337 5215.5,5337
  Bottom Layer w9.8: 4072,5839.4 4117,5794.4 R-SCL1.2@4554.7,5794.4 ; 4347,6169.4 4347,6149.4 4347,6002.2 R-SCL1.2@4554.7,5794.4 ; R3.1@4599.7,5404.4 4599.7,5429.4 4659.7,5489.4 4724.4,5489.4 4824.1,5589.1 4824.1,5604.4 R1.1@4849.1,5629.4 4873.6,5653.9 4904.8,5653.9 ; R2.1@4654.4,5209.7 4709.7,5154.4 5104.1,5154.4 ; A2-1.1@5066.4,5834.4 5066.4,5729.8 5141.8,5654.4 ; Top_PCB.4@5177.6,4880.8 5169.4,4889 R4.1@5169.4,5029.7 5104.1,5095.1 5104.1,5154.4 ; C14.2@5264.4,5512 5226.8,5512 v1(5214.4,5524.4) 5214.4,5605.6 5165.6,5654.4 5141.8,5654.4 ; 3V3.1@5659.4,5154.4 5464.6,5154.4 ; 5842.8,5824.4 5842.8,5758.5 C9.1@5886.8,5714.4 ; MAGNETOMETER_0x1E.3@6682.4,6184.4 6682.4,6152.4 6664.4,6134.4 6472.4,6134.4 5868.9,5530.9 5865.8,5530.9 5859.4,5524.6 5859.4,5521.4 0x45.2@5847.4,5509.4 5811.8,5509.4 5666.8,5364.4 5484.4,5364.4 5464.6,5344.6 5464.6,5154.4 ; MAGNETOMETER_0x1E.3@6682.4,6187.7 6682.4,6195.3 6688.8,6201.7 6696.4,6201.7 6699.2,6204.5 MAGNETOMETER_0x1E.9@6699.2,6243.9 MAGNETOMETER_0x1E.10@6718.9,6243.9 6764.9,6243.9 6779.4,6229.4 v1(6779.4,6199.4) ; C13.2@6727,6314.4 6787,6314.4 C11.2@6794.4,6321.8 6804.5,6321.8 C12.2@6857,6269.4 6874.4,6269.4 v1(6899.4,6244.4) ; MK2_1.2@7091.4,5394.4 7121.8,5394.4 C3.1@7169.4,5346.8 ; R-SCL1.2@4554.7,5794.4 4669.7,5679.4 4884.4,5679.4 4904.8,5659 4904.8,5653.9 ; 4904.8,5653.9 5038.9,5653.9 5039.4,5654.4 5141.8,5654.4 ; 5104.1,5154.4 R-SDA1.2@5104.1,5234.4 5224.1,5114.4 5356.8,5114.4 5396.8,5154.4 5464.6,5154.4
  Bottom Layer w10: A2-1.1@5066.4,5834.4 A1-1.1@5066.4,5879.4 A0-1.1@5066.4,5924.4 ; v1(5192.4,7199.4) MK1_1.2@5212.4,7199.4 ; v1(5279.4,7144.4) 5368.2,7144.4 C1.1@5402,7178.1 ; C16.2@6239.4,4852 6345.8,4852 C15.2@6353.9,4843.9 6388.6,4809.2 ACCEL_0x68.8@6419.9,4809.2 ; ACCEL_0x68.5@6404.4,4734.7 6394.4,4734.7 6359.4,4699.7 6359.4,4644.5 ; ACCEL_0x68.8@6419.4,4809.7 6419.4,4829.4 6429.4,4839.4 6499.4,4839.4 6559.4,4779.4 6559.4,4699.4 6509.4,4649.4 6364.3,4649.4 6359.4,4644.5 ; 6934.1,4319.1 6639.7,4319.1 6359.4,4599.4 6359.4,4644.5
  Bottom Layer w13.8: 5177.6,4246.8 Top_PCB.4@5177.6,4880.8
  Bottom Layer w19.7: MK4.5@3377.8,5409.8 3551.5,5409.8 C7.1@3559.4,5402 ; v1(3589.4,5024.4) 3589.4,5144.4 3769.4,5324.4 3769.4,5429.4 3734.4,5464.4 v1(3699.7,5464.4) 3671.7,5464.4 ; v1(3614.4,4899.4) 3614.4,4719.4 3869.4,4464.4 4960,4464.4 5177.6,4246.8 5177.6,3906.3 ; C8.1@3634.4,5402 C7.1@3559.4,5402 ; MK4_1.2@3702.4,5404.4 3702.4,5433.8 3671.7,5464.4 ; U17.4@4508.1,4183.7 4509.4,4182.4 4509.4,4014.4 4617.6,3906.3 5177.6,3906.3 ; I2C_EXPENDER.16@4899.4,6436.4 5411.4,5924.4 ; A0-1.1@5066.4,5924.4 5411.4,5924.4 ; MK3_1.2@5276.4,3519.4 5336.8,3519.4 C6.1@5351.8,3504.4 ; MK3.5@5339,3377.8 5346.8,3385.6 5346.8,3394.6 5351.8,3399.7 C6.1@5351.8,3504.4 ; C1.1@5402,7178.1 C2.1@5402,7249.4 5409.8,7257.3 MK1.5@5409.8,7371 5413.2,7374.4 v1(5484.4,7374.4) ; v1(5459.4,3614.4) 5374.4,3614.4 5351.8,3591.8 C6.1@5351.8,3504.4 ; TEMP/HUMI_0x40.5@5889.3,5824.4 5842.8,5824.4 v1(5784.4,5824.4) 5511.4,5824.4 5411.4,5924.4 ; C3.1@7169.4,5346.8 C4.1@7240,5346.8 7247.9,5339 MK2.5@7371,5339 7371,4916 7104.4,4649.4 7104.4,4489.4 6934.1,4319.1 6634.4,4019.4 6514.4,4019.4 6084.3,3589.2 6049.6,3589.2 5936.8,3702.1 5381.8,3702.1 v1(5354.4,3729.4) 5177.6,3906.3 ; C7.1@3559.4,5402 3621.8,5464.4 3671.7,5464.4
5V: 5V.1 LED1.2 LED2.2 LED3.2 LED4.2 LED5.2 LED6.2 LED7.2 LED8.2 LED9.2 LED10.2 LED11.2 LED12.2 LED13.2 LED14.2 LED15.2 LED16.4 LEVEL_SHIFFTER-1.5 LEVEL_SHIFFTER-2.5 Top_PCB.3 U17.1 U17.2 | length 19935.8
  Top Layer w10: v1(5129.4,4749.4) 5169.4,4709.4 v1(5464.4,4709.4) ; v1(5669.4,4799.4) 5782.4,4799.4 v1(6009.4,5026.4)
  Top Layer w13.8: v1(3809.4,5243.1) 4193.1,5243.1 4224.4,5274.4 4290.1,5274.4 LED16.4@4327.8,5236.7
  Top Layer w17.7: v1(6904.4,6089.4) 7139.4,6089.4 v1(7144.4,6084.4)
  Top Layer w19.7: v1(4867.8,4387.7) v1(5014.4,4534.4)
  Bottom Layer w10: v1(5014.4,4534.4) 5129.4,4649.4 v1(5129.4,4749.4) ; v1@5128.2,4750.6 5138.2,4760.6 Top_PCB.3@5138.2,4880.8 ; v1(5464.4,4709.4) 5524.4,4649.4 5669.4,4649.4 5724.4,4704.4 5724.4,4714.4 5669.4,4769.4 v1(5669.4,4799.4) ; 5V.1@5884.4,5254.4 5944.4,5254.4 6009.4,5189.4 v1@6009.4,5029.4 ; LED15.2@7316.4,4654.4 LED15.2@7328.7,4642.1
  Bottom Layer w17.7: LEVEL_SHIFFTER-1.5@6473.6,5959.4 6553.6,6039.4 6909.4,6039.4 ; v1(6904.4,6089.4) 6909.4,6084.4 6909.4,6039.4 ; LEVEL_SHIFFTER-2.5@6936.8,5959.8 6936.8,6012 6909.4,6039.4
  Bottom Layer w19.7: LED8.2@3310.9,5684.3 3384.4,5684.3 ; LED9.2@3363.2,4818.2 3418.2,4818.2 3434.4,4834.4 ; LED7.2@3615.3,6496.8 3657.7,6454.4 3674.4,6454.4 ; LED10.2@3763.3,4048.2 3814.5,4099.4 3829.4,4099.4 ; 4358,4387.7 v1(4867.8,4387.7) ; LED11.2@4442,3507.6 4454.4,3520 4454.4,3584.4 ; 4819.4,7249.4 4919.4,7249.4 5031.5,7361.5 LED5.2@5031.5,7432.7 ; 5031.1,3584.4 5226.1,3389.4 LED12.2@5226.1,3298.2 ; 5879.4,7319.4 5898.3,7338.3 LED4.2@5898.3,7394.2 ; 6074.4,3509.4 6137.7,3446.1 LED13.2@6137.7,3432.6 ; 6619.4,6938.3 6648.3,6938.3 6662.2,6952.2 6662.2,6986.9 6674.6,6999.2 LED3.2@6674.6,7006.5 ; 6808.1,3969.4 LED14.2@6861.2,3916.2 ; 7142.2,5619.4 7209.4,5552.2 7447.2,5552.2 LED1.2@7453.2,5546.1 ; 7149.4,6329.4 7218.9,6329.4 LED2.2@7226.3,6336.7 ; 7154.4,4639.4 7169.4,4654.4 LED15.2@7311.7,4654.4
  Bottom Layer w27.6: LED6.2@4223.9,7115.3 4237.1,7102.1 4240,7097.6 ; 4239.99,7097.52 ccw(c4256.6,7108.3) 4249.15,7089.95 ; 4249.2,7090 4319.4,7019.8 4319.4,7019.4
  Bottom Layer w39.4: 3384.4,5684.3 3394.3,5684.3 ; 3674.4,6454.4 3717.1,6454.4 ; U17.1@4271.9,4183.7 4271.9,4384.5 4268.6,4387.7 ; U17.2@4350.7,4183.7 4350.7,4380.4 4358,4387.7 4268.6,4387.7 ; 5879.4,7319.4 6101.8,7097.1 ; 6808.1,3969.4 6659.5,3969.4 ; 7142.2,5619.4 7142.2,6336.6 ; 7149.4,6329.4 7142.2,6336.6 ; 7154.4,4639.4 7154.4,4464.4 6659.5,3969.4 ; 3394.3,5684.3 3459.4,5749.4 3459.4,6196.7 3717.1,6454.4 ; 3394.3,5684.3 3594.5,5684.3 3809.4,5469.4 v1(3809.4,5243.1) 3809.4,5149.4 3494.4,4834.4 3434.4,4834.4 3829.4,4439.4 v1(3829.4,4387.7) ; 3717.1,6454.4 3769.5,6454.4 4564.5,7249.4 4819.4,7249.4 4971.8,7097.1 6101.8,7097.1 ; v1(3829.4,4387.7) 3829.4,4099.4 3939.4,4099.4 4454.4,3584.4 5031.1,3584.4 5039.4,3584.4 5114.4,3659.4 5924.4,3659.4 6074.4,3509.4 6534.4,3969.4 6659.5,3969.4 ; v1(3829.4,4387.7) 4268.6,4387.7 ; 6101.8,7097.1 6260.5,6938.3 6619.4,6938.3 6619.4,6859.4 7142.2,6336.6
$1N3560: LED1.3 LED2.1 | length 1915.7
  Top Layer w10: v1(7205.6,6390.8) 7215.6,6380.8 v1(7215.6,6242.7)
  Top Layer w19.7: v1(7384.4,4704.4) 7423,4743 ; 7423.33,4744.07 ccw(c5374.4,5374.4) 7504.32,5131.73 ; 7504.4,5132.4 v1(7504.4,5514.4)
  Bottom Layer w10: v1(7205.6,6390.8) 7205.6,6372.8 LED2.1@7211.6,6366.8 ; v1(7215.6,6242.7) 7215.6,5942.7 7495.6,5662.7 7495.6,5532.7 LED1.3@7475.6,5512.7
  Bottom Layer w19.7: LED1.3@7455.6,5512.7 7475.6,5512.7 7502.7,5512.7 v1(7504.4,5514.4)
$1N3620: 0x44.2 0x45.1 LIGHT1.2 | length 708.9
  Top Layer w9.8: LIGHT1.2@5374.4,5337 5374.4,5327 5394.4,5307 v1(5674.4,5307)
  Bottom Layer w10: v1(5674.4,5307) 5674.4,5344.4 5811.9,5481.9 5853.9,5481.9 5859.8,5487.8 5863.1,5487.8 5869.5,5494.2 5869.5,5497.4 0x45.1@5881.4,5509.4 0x44.2@5957.4,5509.4
$1N3633: A2-0.1 A2-1.2 I2C_EXPENDER.3 | length 790.8
  Bottom Layer w10: A2-0.1@4984.4,5824.4 4964.4,5804.4 ; A2-1.2@5032.4,5834.4 A2-0.1@4986.4,5834.4 4986.4,5824.4 4966.4,5804.4 4964.4,5804.4 ; 4844.4,5896.4 4844.4,5999.9 4827.1,6017.2 4827.1,6034.7 I2C_EXPENDER.3@4799.4,6062.4 4799.4,5941.4 4844.4,5896.4 ; 4844.4,5896.4 4844.4,5864.4 4904.4,5804.4 4936.4,5804.4 ; 4844.4,5896.4 4936.4,5804.4 ; 4936.4,5804.4 4964.4,5804.4
$1N3634: A1-0.1 A1-1.2 I2C_EXPENDER.2 | length 790
  Top Layer w10: v1(4929.4,5952.4) 4929.4,5942.4 v1(5009.4,5862.4) ; v1(5008.8,5899.7) 5029.4,5920.3 v1(5029.4,5969.4)
  Bottom Layer w10: v1(4929.4,5952.4) 4849.4,6032.4 I2C_EXPENDER.2@4849.4,6062.4 4849.4,6099.4 4884.4,6134.4 4894.4,6134.4 4908.2,6120.6 4908.6,6120.6 4921.7,6107.6 4921.7,6107.1 5029.4,5999.4 v1(5029.4,5969.4) ; v1(5008.8,5899.7) 5008.8,5883 5005.2,5879.4 ; 5005.2,5879.4 A1-0.1@4986.4,5879.4 5003.5,5862.4 v1(5009.4,5862.4) 5015.3,5862.4 A1-1.2@5032.4,5879.4 5005.2,5879.4
$1N3635: A0-0.2 A0-1.2 I2C_EXPENDER.1 | length 220
  Bottom Layer w10: I2C_EXPENDER.1@4899.4,6062.4 4986.4,5975.3 A0-0.2@4986.4,5924.4 A0-1.2@5032.4,5924.4
$1N7419: C10.2 MAGNETOMETER_0x1E.5 | length 111.8
  Bottom Layer w9.8: C10.2@6597,6254.4 6597,6206.1 6598.5,6204.6
  Bottom Layer w10: 6598.5,6204.6 MAGNETOMETER_0x1E.5@6659.9,6204.6
$1N20340: LED2.3 LED3.1 | length 1048.8
  Bottom Layer w10: LED3.1@6648.5,7027.6 6667.6,7046.7 6700.9,7046.7 6760.9,6986.7 6760.9,6876.7 7270.9,6366.7 7270.9,6336.7 LED2.3@7240.9,6306.7
$1N20352: LED3.3 LED4.1 | length 1118.1
  Top Layer w10: v1(5843.1,7402.9) 5923.1,7402.9 6390.6,6935.5 v1(6690.6,6935.5)
  Bottom Layer w10: v1(5843.1,7402.9) LED4.1@5866,7402.9 ; v1(6690.6,6935.5) 6690.6,6975.5 LED3.3@6700.6,6985.5
$1N20367: LED4.3 LED5.1 | length 1045.6
  Top Layer w10: v1(4978.7,7407.5) 4998.7,7427.5 v1(5438.7,7427.5)
  Bottom Layer w10: v1(4978.7,7407.5) LED5.1@4998.4,7427.5 ; v1(5438.7,7427.5) 5458.7,7447.5 5908.7,7447.5 5930.6,7425.6 LED4.3@5930.6,7385.6
$1N20379: LED5.3 LED6.1 | length 1083
  Bottom Layer w10: LED6.1@4195.9,7097 4184.5,7108.4 4184.5,7127.9 4244.5,7187.9 4304.5,7187.9 4404.5,7287.9 4754.5,7287.9 4944.5,7477.9 5034.5,7477.9 5064.5,7447.9 LED5.3@5064.5,7437.9
$1N20458: LED6.3 LED7.1 | length 1099.4
  Top Layer w10: v1(4252,7033.5) v1(4302,7083.5)
  Bottom Layer w10: LED7.1@3597.1,6468.8 3577.1,6488.8 3577.1,6538.6 4072,7033.5 v1(4252,7033.5) ; LED6.3@4252,7133.5 v1(4302,7083.5)
$1N20464: LED7.3 LED8.1 | length 1054.4
  Top Layer w10: v1(3343.5,5654.9) 3343.5,6004.9 3413.5,6074.9 3413.5,6244.9 v1(3663.5,6494.9)
  Bottom Layer w10: LED8.1@3305.6,5651.2 3309.3,5654.9 v1(3343.5,5654.9) ; LED7.3@3633.5,6524.9 v1(3663.5,6494.9)
$1N20663: LED14.3 LED15.1 | length 1255.9
  Bottom Layer w10: LED14.3@6837.6,3892.6 6817.6,3912.6 6807.6,3912.6 6777.6,3882.6 6777.6,3872.6 6817.6,3832.6 6867.6,3832.6 6947.6,3912.6 6947.6,4112.6 7337.6,4502.6 7337.6,4562.6 7367.6,4592.6 7367.6,4646.8 LED15.1@7341.2,4673.2
$1N20669: LED12.3 LED13.1 | length 1111.6
  Bottom Layer w10: LED12.3@5192.7,3300.6 5192.7,3280.6 5222.7,3250.6 5642.7,3250.6 5762.7,3370.6 6132.7,3370.6 6168.7,3406.6 LED13.1@6168.7,3445.2
$1N20676: LED13.3 LED14.1 | length 1085.6
  Top Layer w10: v1(6076.7,3460.1) 6346.7,3460.1 v1(6856.7,3970.1)
  Bottom Layer w10: v1(6076.7,3460.1) 6106.7,3430.1 LED13.3@6106.7,3420.1 ; v1(6856.7,3970.1) 6856.7,3968.1 LED14.1@6884.9,3939.9
$1N20684: LED11.3 LED12.1 | length 1035.2
  Top Layer w10: v1(4412.2,3472.8) 4442.2,3442.8 4692.2,3442.8 4839.1,3295.9 5219.1,3295.9 v1(5259.1,3335.9)
  Bottom Layer w10: v1(4412.2,3472.8) 4402.2,3482.8 4402.2,3512.8 LED11.3@4412.2,3522.8 ; v1(5259.1,3335.9) 5259.1,3296.3 LED12.1@5259.5,3295.9
$1N20691: LED10.3 LED11.1 | length 1075.8
  Top Layer w10: v1(4352.3,3504.3) 4472.3,3504.3 v1(4492.3,3484.3)
  Bottom Layer w10: LED10.3@3742.3,4074.3 3722.3,4054.3 3722.3,4024.3 4092.3,3654.3 4202.3,3654.3 v1(4352.3,3504.3) ; LED11.1@4471.8,3492.4 4480,3484.3 v1(4492.3,3484.3)
$1N20698: LED9.3 LED10.1 | length 1054.8
  Top Layer w10: v1(3394.6,4850.5) 3749.4,4495.7 3749.4,4117.6 v1(3814.6,4052.4)
  Bottom Layer w10: LED9.3@3354.6,4850.5 v1(3394.6,4850.5) ; LED10.1@3784.4,4022.2 v1(3814.6,4052.4)
$1N29816: MK3.2 MK3_0.1 MK3_1.1 | length 379.1
  Top Layer w10: v1(5309.8,3485.4) 5409.8,3385.4 v1(5439.8,3385.4)
  Bottom Layer w10: MK3_0.1@5276.4,3569.4 5276.4,3563.5 5242.4,3529.4 MK3_1.1@5242.4,3519.4 5242.4,3512.9 5269.8,3485.4 v1(5309.8,3485.4) ; MK3.2@5409.8,3345.4 5419.8,3345.4 5439.8,3365.4 v1(5439.8,3385.4)
$1N29900: MK4.2 MK4_0.1 MK4_1.1 | length 486.5
  Bottom Layer w10: MK4.2@3345.4,5339 3345.4,5329 3365.4,5309 3705.4,5309 3736.4,5340 MK4_0.1@3736.4,5349.4 MK4_1.1@3736.4,5404.4
$1N29929: MK2.2 MK2_0.1 MK2_1.1 | length 452.7
  Top Layer w10: v1(7133.4,5414.4) 7273.4,5414.4 7293.4,5394.4 7393.4,5394.4 v1(7403.4,5384.4)
  Bottom Layer w10: MK2_0.1@7057.4,5344.4 MK2_1.1@7057.4,5394.4 7057.4,5398.4 7083.4,5424.4 7123.4,5424.4 v1(7133.4,5414.4) ; v1(7403.4,5384.4) MK2.2@7403.4,5409.8
$1N29958: MK1.2 MK1_0.1 MK1_1.1 | length 248.2
  Bottom Layer w10: MK1_1.1@5246.4,7199.4 MK1_0.1@5246.4,7249.4 5249,7251.9 5249,7323.4 5329,7403.4 MK1.2@5339,7403.4
BCLK: MK1.4 MK2.4 MK3.4 MK4.4 Top_PCB.13 | length 10033
  Top Layer w10: v1(3347.5,5381.9) 3347.5,4770.2 3504.9,4612.9 3504.9,4321.3 3804.9,4021.3 4644.9,4021.3 v1(5314.9,3351.3) 5441.9,3351.3 5601.9,3511.3 5601.9,4741.3 ; v1(5439.8,5183.4) v1(5499.8,5123.4) ; v1(5529.8,5023.4) 5529.8,4933.4 v1(5531.9,4931.3) 5531.9,4811.3 5601.9,4741.3 ; v1(5529.8,7143.4) 5569.8,7103.4 5569.8,5823.4 v1(5539.8,5793.4) ; v1(7401.9,5311.3) 6781.9,4691.3 6521.9,4691.3 6466.8,4746.4 5607,4746.4 5601.9,4741.3
  Bottom Layer w10: MK4.4@3345.4,5409.8 3347.5,5407.8 v1(3347.5,5381.9) ; v1(5314.9,3351.3) 5333.1,3351.3 MK3.4@5339,3345.4 ; MK1.4@5409.8,7403.4 5489.8,7403.4 5529.8,7363.4 v1(5529.8,7143.4) ; v1(5439.8,5183.4) 5439.8,5693.4 v1(5539.8,5793.4) ; v1(5499.8,5123.4) 5499.8,5053.4 v1(5529.8,5023.4) ; Top_PCB.13@5531.9,4880.8 v1(5531.9,4931.3) ; v1(7401.9,5311.3) 7401.9,5337.5 MK2.4@7403.4,5339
